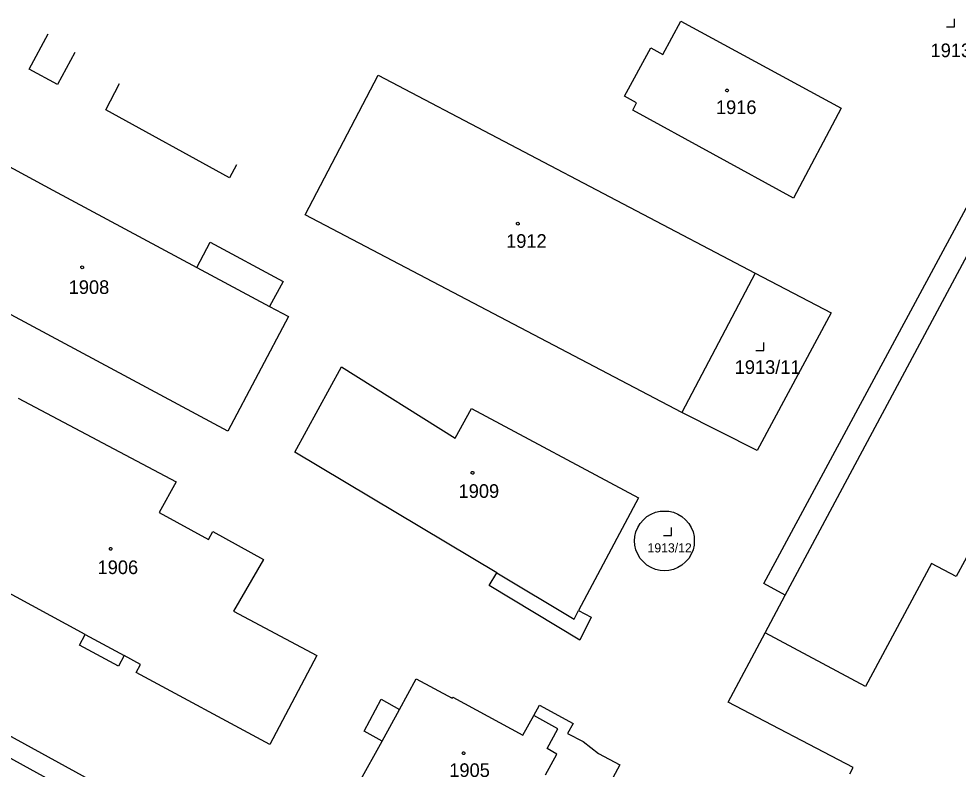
# Model space of a CAD drawing. Extents: x -528274 to -527531, y -1079304 to -1078580.
# Drawn here: x -528123 to -528005.8, y -1078912.6 to -1078819.1 of the extents above; entities that cross this region are included whole.
import ezdxf

# ---------------------------------------------------------------- set-up
doc = ezdxf.new("R2010")
doc.units = 0
doc.layers.add('katastrální mapa', color=7, linetype='Continuous')

msp = doc.modelspace()

# ---------------------------------------------------------------- linework, layer by layer
at = {"layer": 'katastrální mapa'}
for p, q in [((-528042.63, -1078823.54), (-528040.36, -1078819.37)), ((-528040.36, -1078819.37), (-528020.37, -1078830.2)), ((-528121.66, -1078825.37), (-528119.29, -1078820.95)), ((-528047.41, -1078828.74), (-528044.14, -1078822.72)), ((-528044.14, -1078822.72), (-528042.63, -1078823.54)), ((-528115.97, -1078823.27), (-528118.13, -1078827.26)), ((-528118.13, -1078827.26), (-528121.66, -1078825.37)), ((-528087.22, -1078843.53), (-528078.13, -1078826.09)), ((-528078.13, -1078826.09), (-528031.12, -1078850.8)), ((-528112.1, -1078830.42), (-528110.38, -1078827.15)), ((-528045.9, -1078829.56), (-528047.41, -1078828.74)), ((-528046.38, -1078830.45), (-528045.9, -1078829.56)), ((-528096.68, -1078838.9), (-528112.1, -1078830.42)), ((-528026.33, -1078841.43), (-528046.38, -1078830.45)), ((-528020.37, -1078830.2), (-528026.33, -1078841.43)), ((-528030.02, -1078889.48), (-528000.05, -1078833.84)), ((-528124.62, -1078837.25), (-528118.7, -1078840.44)), ((-528095.82, -1078837.28), (-528096.68, -1078838.9)), ((-528118.7, -1078840.44), (-528100.75, -1078850.07)), ((-528027.35, -1078890.91), (-528000.58, -1078840.93)), ((-528040.24, -1078868.14), (-528087.22, -1078843.53)), ((-528096.89, -1078870.48), (-528142.85, -1078845.82)), ((-528100.75, -1078850.07), (-528099.07, -1078846.93)), ((-528099.07, -1078846.93), (-528089.99, -1078851.81)), ((-528100.75, -1078850.07), (-528091.67, -1078854.93)), ((-528031.12, -1078850.8), (-528040.24, -1078868.14)), ((-528031.12, -1078850.8), (-528021.62, -1078855.75)), ((-528089.99, -1078851.81), (-528091.67, -1078854.93)), ((-528091.67, -1078854.93), (-528089.31, -1078856.2)), ((-528089.31, -1078856.2), (-528096.89, -1078870.48)), ((-528021.62, -1078855.75), (-528030.87, -1078872.89)), ((-528088.53, -1078873.12), (-528082.71, -1078862.46)), ((-528082.71, -1078862.46), (-528068.54, -1078871.34)), ((-528123.04, -1078866.35), (-528103.32, -1078876.8)), ((-528068.54, -1078871.34), (-528066.47, -1078867.67)), ((-528066.47, -1078867.67), (-528045.66, -1078878.8)), ((-528030.87, -1078872.89), (-528040.24, -1078868.14)), ((-528063.33, -1078888.15), (-528088.53, -1078873.12)), ((-528103.32, -1078876.8), (-528105.43, -1078880.62)), ((-528045.66, -1078878.8), (-528053.13, -1078892.84)), ((-528105.43, -1078880.62), (-528099.3, -1078883.98)), ((-528099.3, -1078883.98), (-528098.77, -1078883.01)), ((-528098.77, -1078883.01), (-528092.43, -1078886.49)), ((-528003.95, -1078884.78), (-528006.02, -1078888.62)), ((-528114.66, -1078895.83), (-528134.18, -1078885.29)), ((-528092.43, -1078886.49), (-528096.17, -1078892.91)), ((-528009.1, -1078886.97), (-528017.34, -1078902.33)), ((-528006.02, -1078888.62), (-528009.1, -1078886.97)), ((-528064.28, -1078889.74), (-528063.33, -1078888.15)), ((-528063.33, -1078888.15), (-528053.69, -1078893.9)), ((-528027.35, -1078890.91), (-528030.02, -1078889.48)), ((-528052.99, -1078896.53), (-528064.28, -1078889.74)), ((-528029.87, -1078895.62), (-528027.35, -1078890.91)), ((-528096.17, -1078892.91), (-528085.77, -1078898.43)), ((-528053.69, -1078893.9), (-528053.13, -1078892.84)), ((-528053.13, -1078892.84), (-528051.55, -1078893.68)), ((-528051.55, -1078893.68), (-528052.99, -1078896.53)), ((-528115.38, -1078897.15), (-528114.66, -1078895.83)), ((-528114.66, -1078895.83), (-528109.82, -1078898.44)), ((-528034.49, -1078904.25), (-528029.87, -1078895.62)), ((-528017.34, -1078902.33), (-528029.87, -1078895.62)), ((-528110.53, -1078899.76), (-528115.38, -1078897.15)), ((-528109.82, -1078898.44), (-528110.53, -1078899.76)), ((-528107.77, -1078899.55), (-528109.82, -1078898.44)), ((-528085.77, -1078898.43), (-528091.65, -1078909.56)), ((-528108.31, -1078900.55), (-528107.77, -1078899.55)), ((-528091.65, -1078909.56), (-528108.31, -1078900.55)), ((-528075.47, -1078905.17), (-528073.37, -1078901.36)), ((-528073.37, -1078901.36), (-528068.89, -1078903.78)), ((-528068.89, -1078903.78), (-528068.81, -1078903.65)), ((-528068.81, -1078903.65), (-528060.08, -1078908.38)), ((-528069.83, -1078938.11), (-528132.09, -1078904.11)), ((-528079.87, -1078907.89), (-528077.76, -1078903.91)), ((-528077.76, -1078903.91), (-528075.47, -1078905.17)), ((-528058.73, -1078905.94), (-528058.02, -1078904.64)), ((-528058.02, -1078904.64), (-528053.81, -1078906.91)), ((-528018.9, -1078912.43), (-528034.49, -1078904.25)), ((-528077.63, -1078909.11), (-528075.47, -1078905.17)), ((-528060.08, -1078908.38), (-528058.73, -1078905.94)), ((-528055.74, -1078907.58), (-528058.73, -1078905.94)), ((-528007.07, -1078975.18), (-528133.47, -1078906.09)), ((-528053.81, -1078906.91), (-528054.53, -1078908.18)), ((-528077.63, -1078909.11), (-528079.87, -1078907.89)), ((-528057.06, -1078910.06), (-528055.74, -1078907.58)), ((-528054.53, -1078908.18), (-528052.58, -1078909.15)), ((-528080.48, -1078914.29), (-528077.63, -1078909.11)), ((-528052.58, -1078909.15), (-528050.66, -1078910.66)), ((-528057.24, -1078913.31), (-528055.84, -1078910.73)), ((-528055.84, -1078910.73), (-528057.06, -1078910.06)), ((-528050.66, -1078910.66), (-528047.99, -1078912.09)), ((-528047.99, -1078912.09), (-528055.14, -1078925.34)), ((-528019.32, -1078913.22), (-528018.9, -1078912.43))]:
    msp.add_line(p, q, dxfattribs=at)
for points in [[(-528007.26, -1078820.08), (-528006.26, -1078820.08), (-528006.26, -1078819.08)], [(-528031.02, -1078860.42), (-528030.02, -1078860.42), (-528030.02, -1078859.42)], [(-528042.42, -1078887.88), (-528042.95, -1078887.85), (-528043.53, -1078887.72), (-528044.09, -1078887.49), (-528044.6, -1078887.18), (-528045.05, -1078886.79), (-528045.44, -1078886.34), (-528045.75, -1078885.83), (-528045.98, -1078885.27), (-528046.11, -1078884.69), (-528046.14, -1078884.16), (-528046.11, -1078883.63), (-528045.98, -1078883.05), (-528045.75, -1078882.49), (-528045.44, -1078881.98), (-528045.05, -1078881.53), (-528044.6, -1078881.14), (-528044.09, -1078880.83), (-528043.53, -1078880.6), (-528042.95, -1078880.47), (-528042.42, -1078880.44)], [(-528042.42, -1078880.44), (-528041.89, -1078880.47), (-528041.31, -1078880.6), (-528040.75, -1078880.83), (-528040.24, -1078881.14), (-528039.79, -1078881.53), (-528039.4, -1078881.98), (-528039.09, -1078882.49), (-528038.86, -1078883.05), (-528038.73, -1078883.63), (-528038.7, -1078884.16), (-528038.73, -1078884.69), (-528038.86, -1078885.27), (-528039.09, -1078885.83), (-528039.4, -1078886.34), (-528039.79, -1078886.79), (-528040.24, -1078887.18), (-528040.75, -1078887.49), (-528041.31, -1078887.72), (-528041.89, -1078887.85), (-528042.42, -1078887.88)], [(-528042.53, -1078883.51), (-528041.53, -1078883.51), (-528041.53, -1078882.51)]]:
    msp.add_lwpolyline(points, dxfattribs=at)
for points in [[(-528034.62, -1078827.84), (-528034.52, -1078827.86), (-528034.47, -1078827.95), (-528034.45, -1078828.01), (-528034.47, -1078828.1), (-528034.55, -1078828.17), (-528034.62, -1078828.18), (-528034.71, -1078828.15), (-528034.77, -1078828.09), (-528034.79, -1078828.01), (-528034.77, -1078827.92), (-528034.69, -1078827.85)], [(-528060.71, -1078844.45), (-528060.61, -1078844.47), (-528060.56, -1078844.56), (-528060.54, -1078844.62), (-528060.56, -1078844.71), (-528060.64, -1078844.78), (-528060.71, -1078844.79), (-528060.8, -1078844.76), (-528060.86, -1078844.7), (-528060.88, -1078844.62), (-528060.86, -1078844.53), (-528060.78, -1078844.46)], [(-528115.05, -1078849.89), (-528114.95, -1078849.91), (-528114.9, -1078850), (-528114.88, -1078850.06), (-528114.9, -1078850.15), (-528114.98, -1078850.22), (-528115.05, -1078850.23), (-528115.14, -1078850.2), (-528115.2, -1078850.14), (-528115.22, -1078850.06), (-528115.2, -1078849.97), (-528115.12, -1078849.9)], [(-528066.36, -1078875.5), (-528066.26, -1078875.52), (-528066.21, -1078875.61), (-528066.19, -1078875.67), (-528066.21, -1078875.76), (-528066.29, -1078875.83), (-528066.36, -1078875.84), (-528066.45, -1078875.81), (-528066.51, -1078875.75), (-528066.53, -1078875.67), (-528066.51, -1078875.58), (-528066.43, -1078875.51)], [(-528111.49, -1078884.99), (-528111.39, -1078885.01), (-528111.34, -1078885.1), (-528111.32, -1078885.16), (-528111.34, -1078885.25), (-528111.42, -1078885.32), (-528111.49, -1078885.33), (-528111.58, -1078885.3), (-528111.64, -1078885.24), (-528111.66, -1078885.16), (-528111.64, -1078885.07), (-528111.56, -1078885)], [(-528067.48, -1078910.46), (-528067.38, -1078910.48), (-528067.33, -1078910.57), (-528067.31, -1078910.63), (-528067.33, -1078910.72), (-528067.41, -1078910.79), (-528067.48, -1078910.8), (-528067.57, -1078910.77), (-528067.63, -1078910.71), (-528067.65, -1078910.63), (-528067.63, -1078910.54), (-528067.55, -1078910.47)]]:
    msp.add_lwpolyline(points, close=True, dxfattribs=at)

# ---------------------------------------------------------------- texts
for s, height, p in [('1913/1', 1.7, (-528009.23, -1078823.86)), ('1916', 1.7, (-528036, -1078830.95)), ('1912', 1.7, (-528062.17, -1078847.63)), ('1908', 1.7, (-528116.73, -1078853.38)), ('1913/11', 1.7, (-528033.66, -1078863.35)), ('1909', 1.7, (-528068.1, -1078878.8)), ('1913/12', 1.14, (-528044.53, -1078885.6)), ('1906', 1.7, (-528113.13, -1078888.3)), ('1905', 1.7, (-528069.26, -1078913.59))]:
    msp.add_text(s, height=height, dxfattribs=at).set_placement(p)

doc.saveas('drawing.dxf')
